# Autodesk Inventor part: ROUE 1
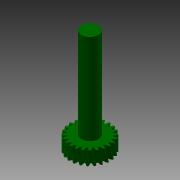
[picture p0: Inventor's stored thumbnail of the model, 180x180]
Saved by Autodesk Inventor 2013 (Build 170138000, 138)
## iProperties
Created: 2012-12
Part Number: ROUE 1
Material: Générique
Document SubType Name: Modeling
Designer: jost thierry
Density: 1 g/cm^3
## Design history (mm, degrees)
node "ROUE 11"
node "ROUE 1"
node "Base1"
